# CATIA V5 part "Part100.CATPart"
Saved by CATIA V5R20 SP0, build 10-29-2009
Part number: FA 063200-2 - comprimido
Revision: ANY
Definition: UNKNOWN
Nomenclature: FA 063200-2 - comprimido
Source: Unknown
Bounding box of the stored display mesh (mm): x -1.95 to 1.95, y 0 to 5.85, z -1.95 to 1.95
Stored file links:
  C:\Users\Utente\Desktop\IO LAVORO\3D X SITO CF\CUMSA\3D files FA\FA 063205-20\Part100.CATPart

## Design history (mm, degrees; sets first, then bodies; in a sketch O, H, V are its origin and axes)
Body1 "Cortar-Extruir1" (main body)
  Solid1: solid without history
